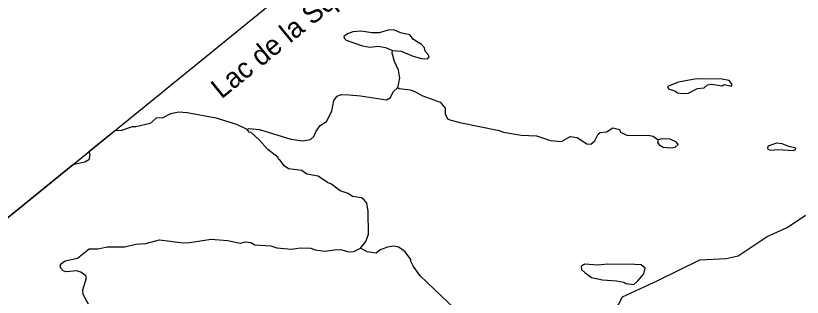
# Model space of a CAD drawing. Extents: x 347059 to 352153, y 6073752 to 6078601.
# Drawn here: x 350791.7 to 351006.5, y 6077503 to 6077579.9 of the extents above; entities that cross this region are included whole.
import ezdxf

# ---------------------------------------------------------------- set-up
doc = ezdxf.new("R2010")
doc.units = 0
doc.layers.add('Level 63', color=7, linetype='Continuous')

msp = doc.modelspace()

# ---------------------------------------------------------------- linework, layer by layer
at = {"layer": 'Level 63'}
msp.add_lwpolyline([(350822.11, 6077057.72), (351218.14, 6077379.8), (350976.59, 6077676.83), (350580.55, 6077354.75)], close=True, dxfattribs=at)
for points in [[(350894.57, 6077570.41), (350896.91, 6077570.21), (350900.19, 6077568.8), (350902.48, 6077568.24), (350904.11, 6077568.13), (350904.62, 6077568.61), (350904.3, 6077569.33), (350903.46, 6077570.21), (350903.3, 6077571.14), (350902.51, 6077572.06), (350900.35, 6077573.37), (350899.28, 6077574.64), (350896.76, 6077575.19), (350894.95, 6077576.05), (350893.4, 6077575.97), (350890.9, 6077575.23), (350888.98, 6077575.2), (350885.95, 6077575.67), (350883.78, 6077575.44), (350882.31, 6077574.94), (350881.32, 6077574.25), (350881.35, 6077573.79), (350881.91, 6077573.17), (350886.35, 6077571.62), (350888.4, 6077571.27), (350890.67, 6077571.58), (350892.67, 6077571.19), (350894.57, 6077570.41)], [(350896.04, 6077560.32), (350896.53, 6077562.8), (350896.17, 6077565.03), (350895.1, 6077567.34), (350894.52, 6077569.64), (350894.57, 6077570.41)], [(350972.39, 6077558.85), (350973.95, 6077558.61), (350975.41, 6077558.7), (350977.85, 6077560.03), (350979.69, 6077560.16), (350980.61, 6077560.96), (350981.78, 6077561.22), (350984.63, 6077560.77), (350985.12, 6077561.08), (350987.07, 6077560.65), (350987.36, 6077561.12), (350986.49, 6077562.22), (350984.62, 6077562.55), (350977.59, 6077562.65), (350972.65, 6077561.72), (350969.69, 6077560.55), (350969.93, 6077559.92), (350971.84, 6077559.23), (350972.39, 6077558.85)], [(350854.86, 6077548.81), (350855.39, 6077549.06), (350858.27, 6077548.79), (350866.81, 6077546.13), (350870.03, 6077545.73), (350872.21, 6077546.05), (350873.12, 6077546.85), (350873.72, 6077548.36), (350874.82, 6077549.86), (350876.55, 6077550.97), (350878.04, 6077553.83), (350878.54, 6077556.72), (350879.5, 6077557.88), (350880.6, 6077558.33), (350882.74, 6077558.29), (350885.79, 6077558), (350892.97, 6077556.88), (350894.06, 6077557.56), (350894.8, 6077559.11), (350896.04, 6077560.32)], [(350896.04, 6077560.32), (350896.41, 6077560.04), (350899.41, 6077559.62), (350900.67, 6077559.15), (350902.58, 6077558.05), (350907.59, 6077556.28), (350908.93, 6077554.66), (350908.96, 6077553.07), (350909.57, 6077551.76), (350910.21, 6077551.45), (350912.98, 6077550.7), (350923.67, 6077548.5), (350924.84, 6077548.04), (350929.69, 6077547.21), (350933.86, 6077547.05), (350937.71, 6077545.84), (350940.76, 6077545.55), (350943.06, 6077546.86), (350944.99, 6077546.66), (350947.64, 6077544.92), (350948.77, 6077544.83), (350949.87, 6077545.69), (350950.7, 6077547.54), (350951.3, 6077548.01), (350953.05, 6077548.16), (350954.78, 6077549.26), (350956.53, 6077548.77), (350956.81, 6077548.1), (350958.58, 6077547.29), (350962.56, 6077547.16), (350964.4, 6077547.29), (350965.72, 6077546.94), (350967.1, 6077546)], [(350871.16, 6077536.59), (350869.83, 6077537.57), (350866.21, 6077538.07), (350864.99, 6077538.9), (350863.79, 6077540.55), (350863.44, 6077540.69), (350863.36, 6077541.11), (350860.5, 6077543.33), (350858.27, 6077545.88), (350855.99, 6077547.98), (350855.45, 6077548.05), (350854.86, 6077548.81), (350852.08, 6077550.2), (350846.42, 6077551.86), (350838.47, 6077553.35), (350836.22, 6077553.54), (350833.98, 6077553.09), (350831.89, 6077552.03), (350830.01, 6077551.86), (350828.42, 6077550.47), (350824.48, 6077549.5), (350823.44, 6077549.5), (350820.54, 6077548.54), (350818.76, 6077548.48), (350811.63, 6077542.68), (350811.71, 6077542.64), (350811.89, 6077541.89), (350811.63, 6077540.55), (350810.6, 6077539.91), (350807.3, 6077539.15), (350726.47, 6077473.42)], [(350968.09, 6077546.28), (350967.1, 6077546), (350966.92, 6077545.29), (350967.43, 6077544.64), (350968.49, 6077544.01), (350970.51, 6077543.8), (350971.76, 6077543.96), (350972.54, 6077544.73), (350972.12, 6077545.37), (350970.44, 6077546.17), (350968.09, 6077546.28)], [(350999.45, 6077545.06), (350997.17, 6077544.25), (350996.97, 6077543.78), (350997.11, 6077543.4), (350997.8, 6077543.13), (350999.83, 6077543.33), (351004.02, 6077543.03), (351004.6, 6077543.32), (351004.7, 6077543.72), (351002.8, 6077544.19), (351001.02, 6077544.91), (350999.45, 6077545.06)], [(350811.02, 6077508.3), (350810.82, 6077508.87), (350809.44, 6077509.82), (350808.35, 6077510.18), (350805.49, 6077509.9), (350804.62, 6077510.19), (350803.9, 6077511.01), (350803.9, 6077512.05), (350805.23, 6077512.93), (350808.55, 6077513.65), (350811.74, 6077516.21), (350814.19, 6077516.18), (350816.67, 6077516.74), (350821.44, 6077516.73), (350824.49, 6077517.49), (350827.2, 6077517.65), (350830.96, 6077518.64), (350837.45, 6077517.87), (350839.19, 6077517.93), (350845.08, 6077518.88), (350849.53, 6077518.46), (350853.08, 6077517.74), (350854.44, 6077518.07), (350855.92, 6077517.93), (350856.98, 6077517.3), (350861.35, 6077516.98), (350862.97, 6077516.46), (350866.97, 6077516.1), (350869.34, 6077516.49), (350872.28, 6077516.35), (350873.5, 6077515.93), (350876.1, 6077515.6), (350878.64, 6077515.97), (350880.33, 6077515.98), (350882.66, 6077515.37), (350883.99, 6077515.44), (350885.83, 6077516.39), (350887.33, 6077518.2), (350887.99, 6077520.17), (350887.9, 6077526.41), (350887.59, 6077528.67), (350886.72, 6077529.69), (350886.14, 6077530.13), (350883.68, 6077530.48), (350882.43, 6077531.36), (350880.24, 6077532.09), (350877.87, 6077533.89), (350876.83, 6077534.29), (350874.24, 6077536.07), (350871.16, 6077536.59)], [(350946.7, 6077472.06), (350945.16, 6077477.98), (350945.44, 6077481.67), (350947.86, 6077485.74), (350955.59, 6077495.23), (350955.41, 6077499.3), (350957.39, 6077503.1), (350966.84, 6077507.47), (350978.47, 6077513.21), (350985.7, 6077513.58), (350988.93, 6077514.31), (350996.87, 6077519.6), (351002.31, 6077522.06), (351007.37, 6077525.43)], [(350905.67, 6077485.49), (350904.49, 6077486.92), (350903.79, 6077489.37), (350904.62, 6077490.17), (350905.36, 6077490.26), (350906.17, 6077490.98), (350907.55, 6077493.58), (350908.71, 6077494.89), (350911.88, 6077497.36), (350912.03, 6077498.93), (350911.72, 6077499.75), (350902.17, 6077508.8), (350900.35, 6077511.35), (350899.58, 6077512.86), (350899.55, 6077513.31), (350898.03, 6077515.37), (350896.95, 6077516.23), (350896.19, 6077516.69), (350894.9, 6077516.89), (350893.23, 6077516.65), (350891.23, 6077515.9), (350890.12, 6077515.04), (350887.7, 6077515.34), (350885.83, 6077516.39)], [(350946.99, 6077511.99), (350946.1, 6077511.38), (350946.22, 6077510.59), (350947.15, 6077509.61), (350948.91, 6077508.39), (350951.92, 6077507.74), (350955.75, 6077507.49), (350957.7, 6077507.06), (350958.29, 6077506.72), (350960.44, 6077506.45), (350961.61, 6077507.44), (350963.21, 6077509.33), (350963.54, 6077510.88), (350962.48, 6077511.83), (350960.77, 6077511.96), (350953.27, 6077512.03), (350950.69, 6077511.71), (350946.99, 6077511.99)], [(350811.57, 6077501.05), (350810.08, 6077503.69), (350810.02, 6077505.01), (350811.02, 6077508.3)]]:
    msp.add_lwpolyline(points, dxfattribs=at)

# ---------------------------------------------------------------- texts
msp.add_text('Lac de la Squaw', height=5.5, rotation=39.1198, dxfattribs=at).set_placement((350847.86, 6077556.98))

doc.saveas('drawing.dxf')
